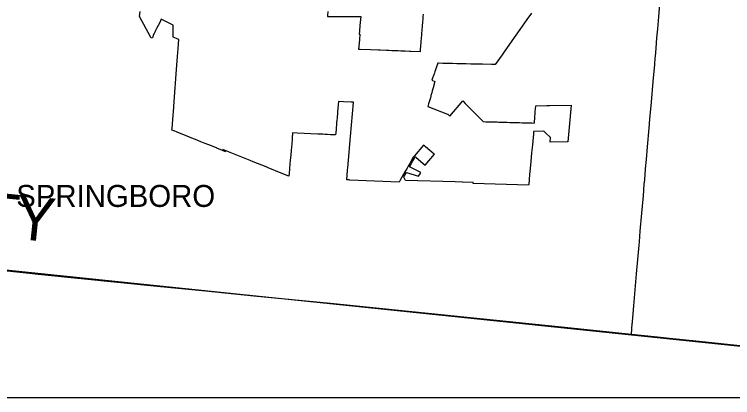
# Model space of a CAD drawing. Extents: x 0 to 34, y 0 to 22.
# Drawn here: x 5.1855 to 5.4485, y 14.1 to 14.2404 of the extents above; entities that cross this region are included whole.
import ezdxf

# ---------------------------------------------------------------- set-up
doc = ezdxf.new("R2010")
doc.units = 0
for name, color, linetype in [('GM_X_Corporation', 7, 'Continuous'), ('GM_X_Corporation_Text', 7, 'Continuous'), ('GM_X_County', 7, 'Continuous'), ('GM_X_County_Text', 7, 'Continuous'), ('GM_X_State_Route', 7, 'Continuous'), ('SC_Scratch1', 7, 'Continuous'), ('SH_Data', 7, 'Continuous')]:
    doc.layers.add(name, color=color, linetype=linetype)

msp = doc.modelspace()

# ---------------------------------------------------------------- linework, layer by layer
at = {"layer": 'GM_X_Corporation'}
for points in [[(5.37488, 14.24084), (5.37323, 14.2385), (5.37064, 14.23482), (5.36773, 14.23069), (5.36489, 14.22666), (5.36412, 14.22557), (5.36159, 14.22197), (5.36152, 14.22197), (5.3614, 14.22197), (5.36101, 14.22198), (5.36089, 14.22198), (5.3603, 14.222), (5.36021, 14.222), (5.35698, 14.22207), (5.3565, 14.22208), (5.35642, 14.22208), (5.35558, 14.2221), (5.35465, 14.22212), (5.35268, 14.22217), (5.35099, 14.2222), (5.35071, 14.22221), (5.34931, 14.22224), (5.34878, 14.22225), (5.34762, 14.22228), (5.34749, 14.22228), (5.34593, 14.22231), (5.34425, 14.22235), (5.34256, 14.22239), (5.34245, 14.22239), (5.34085, 14.22243), (5.34054, 14.22243), (5.34053, 14.22243), (5.3401, 14.22116), (5.33973, 14.22008), (5.3395, 14.21939), (5.33946, 14.21927), (5.33931, 14.21884), (5.33922, 14.21855), (5.33889, 14.21759), (5.3388, 14.21734), (5.33842, 14.21622), (5.3395, 14.2158), (5.33883, 14.21342), (5.33852, 14.21231), (5.33834, 14.21166), (5.33805, 14.21061), (5.33798, 14.21036), (5.33798, 14.21036), (5.33784, 14.20984), (5.33763, 14.2091), (5.33722, 14.20763), (5.33694, 14.20661), (5.33692, 14.20656), (5.34418, 14.2038), (5.34419, 14.2038), (5.3443, 14.20377), (5.34495, 14.20303), (5.345, 14.2031), (5.34975, 14.20865), (5.35062, 14.20777), (5.35338, 14.20496), (5.35597, 14.20232), (5.35597, 14.20232), (5.35664, 14.20163), (5.35666, 14.20161), (5.35719, 14.20107), (5.35813, 14.20105), (5.35965, 14.20101), (5.3597, 14.20101), (5.36097, 14.20097), (5.36106, 14.20097), (5.36194, 14.20095), (5.36202, 14.20095), (5.36219, 14.20094), (5.36228, 14.20094), (5.36291, 14.20092), (5.36299, 14.20092), (5.36387, 14.2009), (5.36396, 14.2009), (5.36486, 14.20087), (5.36498, 14.20087), (5.36596, 14.20084), (5.36691, 14.20081), (5.36694, 14.20081), (5.368, 14.20078), (5.36921, 14.20075), (5.37043, 14.20072), (5.37045, 14.20072), (5.37143, 14.20069), (5.37277, 14.20065), (5.37468, 14.2006), (5.37496, 14.20059), (5.37592, 14.20057), (5.37594, 14.20087), (5.37608, 14.20246), (5.37625, 14.20444), (5.37629, 14.20492), (5.37635, 14.20564), (5.37645, 14.20684), (5.38052, 14.20692), (5.38165, 14.20695), (5.38938, 14.20711), (5.38825, 14.19369), (5.38171, 14.19355), (5.38187, 14.19525), (5.38004, 14.19696), (5.37943, 14.19753), (5.37566, 14.19747), (5.37557, 14.19656), (5.3752, 14.19259), (5.37493, 14.18961), (5.37464, 14.18653), (5.3744, 14.18393), (5.37419, 14.18173), (5.37386, 14.17809), (5.37383, 14.17778), (5.35355, 14.17843), (5.35354, 14.17843), (5.35356, 14.17869), (5.35357, 14.17876), (5.34956, 14.17889), (5.34953, 14.17889), (5.34691, 14.17897), (5.34688, 14.17897), (5.32879, 14.17956), (5.32812, 14.18076), (5.32829, 14.18105), (5.32907, 14.18244), (5.3291, 14.18248), (5.33355, 14.18105), (5.33408, 14.18198), (5.33426, 14.18229), (5.33435, 14.18245), (5.3336, 14.18282), (5.33025, 14.18449), (5.33024, 14.1845), (5.33078, 14.18544), (5.33071, 14.18548), (5.33101, 14.18601), (5.33129, 14.18649), (5.33199, 14.18774), (5.33222, 14.188), (5.33238, 14.18819), (5.33239, 14.18819), (5.33271, 14.18791), (5.33593, 14.18519), (5.33597, 14.18515), (5.33934, 14.18914), (5.33929, 14.18918), (5.33609, 14.1919), (5.33575, 14.19218), (5.33539, 14.19249), (5.33201, 14.18851), (5.33159, 14.18802), (5.33029, 14.18572), (5.32974, 14.18475), (5.32934, 14.18405), (5.3288, 14.1831), (5.32855, 14.18265), (5.32694, 14.17983), (5.32642, 14.17891), (5.3264, 14.17891), (5.30837, 14.17969), (5.30812, 14.1797), (5.30721, 14.17974), (5.30753, 14.18332), (5.30754, 14.18332), (5.30772, 14.18526), (5.30775, 14.1856), (5.30786, 14.1869), (5.30861, 14.19563), (5.30967, 14.20806), (5.30968, 14.20816), (5.30966, 14.20816), (5.30964, 14.20816), (5.30941, 14.20818), (5.30915, 14.20819), (5.30905, 14.20819), (5.30905, 14.20819), (5.30904, 14.20819), (5.30904, 14.2082), (5.30903, 14.2082), (5.30903, 14.2082), (5.30879, 14.20821), (5.30607, 14.20835), (5.30418, 14.20844), (5.30408, 14.20726), (5.30403, 14.20662), (5.30401, 14.2064), (5.30383, 14.2043), (5.30367, 14.20241), (5.30366, 14.20232), (5.3036, 14.20161), (5.30353, 14.20075), (5.30349, 14.20028), (5.30345, 14.19987), (5.30337, 14.19895), (5.30333, 14.19846), (5.30331, 14.19824), (5.3033, 14.19804), (5.30314, 14.1962), (5.30244, 14.19623), (5.30128, 14.19629), (5.30024, 14.19634), (5.29993, 14.19636), (5.29935, 14.19639), (5.29925, 14.19639), (5.29847, 14.19643), (5.29759, 14.19647), (5.29741, 14.19648), (5.29704, 14.1965), (5.2967, 14.19652), (5.29661, 14.19652), (5.29409, 14.19664), (5.29158, 14.19677), (5.28904, 14.19689), (5.28742, 14.19697), (5.2874, 14.19697), (5.28733, 14.19611), (5.2873, 14.19575), (5.28721, 14.19462), (5.28721, 14.19454), (5.28697, 14.19159), (5.28688, 14.19066), (5.28672, 14.18874), (5.28656, 14.187), (5.2863, 14.18399), (5.28611, 14.18184), (5.2861, 14.18168), (5.28607, 14.18141), (5.28605, 14.18111), (5.28321, 14.18226), (5.27842, 14.18421), (5.27777, 14.18447), (5.27298, 14.18641), (5.27184, 14.18687), (5.26396, 14.19005), (5.26186, 14.1909), (5.26211, 14.19069), (5.26221, 14.1906), (5.26241, 14.19043), (5.26286, 14.19006), (5.26286, 14.19006), (5.26172, 14.19052), (5.25969, 14.19134), (5.25947, 14.19143), (5.25668, 14.19256), (5.25505, 14.19321), (5.25384, 14.1937), (5.25188, 14.19449), (5.25114, 14.19479), (5.24969, 14.19538), (5.24966, 14.19539), (5.24508, 14.19724), (5.24407, 14.19765), (5.24393, 14.19771), (5.24324, 14.19799), (5.24323, 14.19799), (5.24328, 14.19857), (5.24369, 14.20349), (5.24378, 14.2046), (5.24407, 14.20847), (5.24492, 14.22019), (5.24526, 14.22496), (5.24548, 14.22788), (5.24571, 14.23109), (5.24532, 14.23126), (5.24483, 14.23146), (5.24366, 14.23195), (5.24362, 14.23518), (5.24361, 14.23635), (5.23932, 14.23855), (5.23873, 14.23739), (5.23759, 14.23515), (5.23725, 14.23449), (5.23703, 14.23406), (5.23665, 14.2333), (5.23645, 14.23292), (5.23609, 14.23181), (5.23596, 14.23178), (5.23555, 14.23168), (5.2353, 14.23214), (5.23131, 14.23958), (5.23155, 14.24141)], [(5.30036, 14.24146), (5.30024, 14.23998), (5.30021, 14.23957), (5.30163, 14.23957), (5.30482, 14.23955), (5.30768, 14.23954), (5.31085, 14.23953), (5.3118, 14.23952), (5.31192, 14.23953), (5.31237, 14.23952), (5.31208, 14.2363), (5.31189, 14.23415), (5.31179, 14.23309), (5.31205, 14.23308), (5.31187, 14.23113), (5.31174, 14.22986), (5.31152, 14.22763), (5.31153, 14.22763), (5.31178, 14.22762), (5.312, 14.22761), (5.31209, 14.22761), (5.31589, 14.22746), (5.31881, 14.22735), (5.31942, 14.22733), (5.32177, 14.22724), (5.3226, 14.22721), (5.32377, 14.22716), (5.32495, 14.22712), (5.32571, 14.22709), (5.32608, 14.22707), (5.32698, 14.22704), (5.32863, 14.22697), (5.33018, 14.22691), (5.33066, 14.2269), (5.3342, 14.22676), (5.33421, 14.22679), (5.33427, 14.22759), (5.33436, 14.22875), (5.33448, 14.23015), (5.33449, 14.23027), (5.3346, 14.23172), (5.33469, 14.23276), (5.33472, 14.23316), (5.33473, 14.23331), (5.33484, 14.2346), (5.33495, 14.23604), (5.33496, 14.23618), (5.33507, 14.23748), (5.33517, 14.23877), (5.33519, 14.23893), (5.33519, 14.23898), (5.33523, 14.23949), (5.3353, 14.24037)]]:
    msp.add_lwpolyline(points, dxfattribs=at)
at = {"layer": 'GM_X_County'}
msp.add_lwpolyline([(5.54353, 14.10916), (5.43403, 14.12076), (5.43391, 14.12077), (5.4254, 14.12167), (5.42109, 14.12213), (5.41148, 14.12315), (5.40457, 14.12386), (5.38582, 14.12578), (5.30127, 14.13447), (5.27317, 14.13721), (5.25545, 14.13896), (5.23782, 14.14067), (5.19422, 14.14514), (5.19105, 14.14547), (5.17815, 14.14679)], dxfattribs=at)
at = {"layer": 'GM_X_State_Route'}
msp.add_line((5.41621, 14.17816), (5.41635, 14.17981), dxfattribs=at)
for points in [[(5.41635, 14.17981), (5.41669, 14.18375), (5.41699, 14.18715), (5.41738, 14.1919), (5.41797, 14.19871), (5.41826, 14.202), (5.41881, 14.20819), (5.41943, 14.21577), (5.42, 14.22204), (5.4202, 14.22443), (5.42024, 14.22488), (5.42051, 14.22795), (5.42084, 14.23181), (5.42111, 14.23502), (5.42147, 14.23945), (5.42204, 14.24593), (5.42224, 14.24821)], [(5.41438, 14.15706), (5.41474, 14.16094), (5.41531, 14.16757), (5.41586, 14.17391), (5.41621, 14.17816)], [(5.4115, 14.1231), (5.41179, 14.12714), (5.41182, 14.12753), (5.41185, 14.12787), (5.41235, 14.13357), (5.41334, 14.14529), (5.41427, 14.15589), (5.41438, 14.15706)]]:
    msp.add_lwpolyline(points, dxfattribs=at)
at = {"layer": 'SC_Scratch1'}
msp.add_lwpolyline([(5.64782, 14.38178), (5.65607, 14.38013), (5.65632, 14.37998), (5.65693, 14.37543), (5.65599, 14.36641), (5.65545, 14.36222), (5.65483, 14.358), (5.65426, 14.3564), (5.65376, 14.35074), (5.65203, 14.33016), (5.6389, 14.18271), (5.63231, 14.10134), (5.63233, 14.10134), (5.57127, 14.10622), (4.8533, 14.18087)], dxfattribs=at)
at = {"layer": 'SH_Data'}
msp.add_line((2.1, 14.1), (8.9, 14.1), dxfattribs=at)

# ---------------------------------------------------------------- texts
at = {"layer": 'GM_X_Corporation_Text'}
msp.add_text('SPRINGBORO', height=0.008037, rotation=0, dxfattribs=at).set_placement((5.18618, 14.16984))
at = {"layer": 'GM_X_County_Text'}
for s, rotation, p in [('T', 354.1335, (5.17335, 14.1595)), ('Y', 354.1343, (5.18531, 14.15827))]:
    msp.add_text(s, height=0.01607, rotation=rotation, dxfattribs=at).set_placement(p)

doc.saveas('drawing.dxf')
